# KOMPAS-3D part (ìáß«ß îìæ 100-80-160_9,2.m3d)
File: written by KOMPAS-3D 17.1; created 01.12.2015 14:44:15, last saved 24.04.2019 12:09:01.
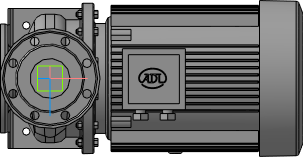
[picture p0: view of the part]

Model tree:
1. Операция без истории:2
